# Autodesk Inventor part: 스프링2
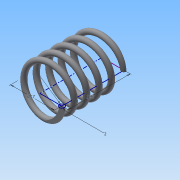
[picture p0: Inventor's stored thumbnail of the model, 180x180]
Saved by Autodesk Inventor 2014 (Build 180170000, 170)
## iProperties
Created: 2016-01
Part Number: 스프링2
Material: 강철, 탄소
Document SubType Name: Modeling
Designer: Administrator
Density: 7.87 g/cm^3
Appearance: 반연마
Mass: 6.46669 g
Surface Area: 16.7182 cm^2
Volume: 0.821689 cm^3
Author: Administrator
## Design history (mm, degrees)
sketch "스케치1"
  geometry: L1 (0, 0)-(8.5, 0); L2 (8.5, 0)-(8.5, 20.5); L3 (8.5, 20.5)-(0, 20.5); L4 (0, 20.5)-(0, 0); C1 r 1 at (8.5, 0)
  constraints: 8 end point, 2 parallel, 1 centre point, 1 coincident, 1 horizontal, 1 perpendicular
  dimensions: "d0" = 2 diameter of C1; "d1" = 17 diameter of L2 L4; "d2" = 20.5 distance of L1.end L2.end (derived)
feature "코일1" sketch "스케치1" pitch "d3" = 10; turns "d5" = 5; dims "d4" = 20.5 (= d2), "d6" = 0, angle "d7" = 90 deg, angle "d8" = 90 deg, "d9" = 0, "d10" = 0
node "작업 평면1"
sketch "스케치2"
  geometry: L1 (-9.5, 0)-(-7.5, 0) reference; L2 (-9.5, 0)-(-7.5, 0) reference; 1 further point
  constraints: 2 horizontal alignment
extrude "돌출1" cut sketch "스케치2" stored distance "d12" = 10; taper "d13" = 0 deg
node "작업 평면2"
sketch "스케치3"
  geometry: L1 (-7.5, 0)-(-9.5, 0) reference; 1 further point
  constraints: 1 horizontal alignment
extrude "돌출2" cut sketch "스케치3" stored distance "d15" = 10; taper "d16" = 0 deg
node "솔리드1"
node "절단 모서리 투영1"
node "절단 모서리 투영2"
node "절단 모서리 투영3"
other parameters: "d11" = 0, "d14" = 20.5 (= d2)
